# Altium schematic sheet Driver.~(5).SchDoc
size A4
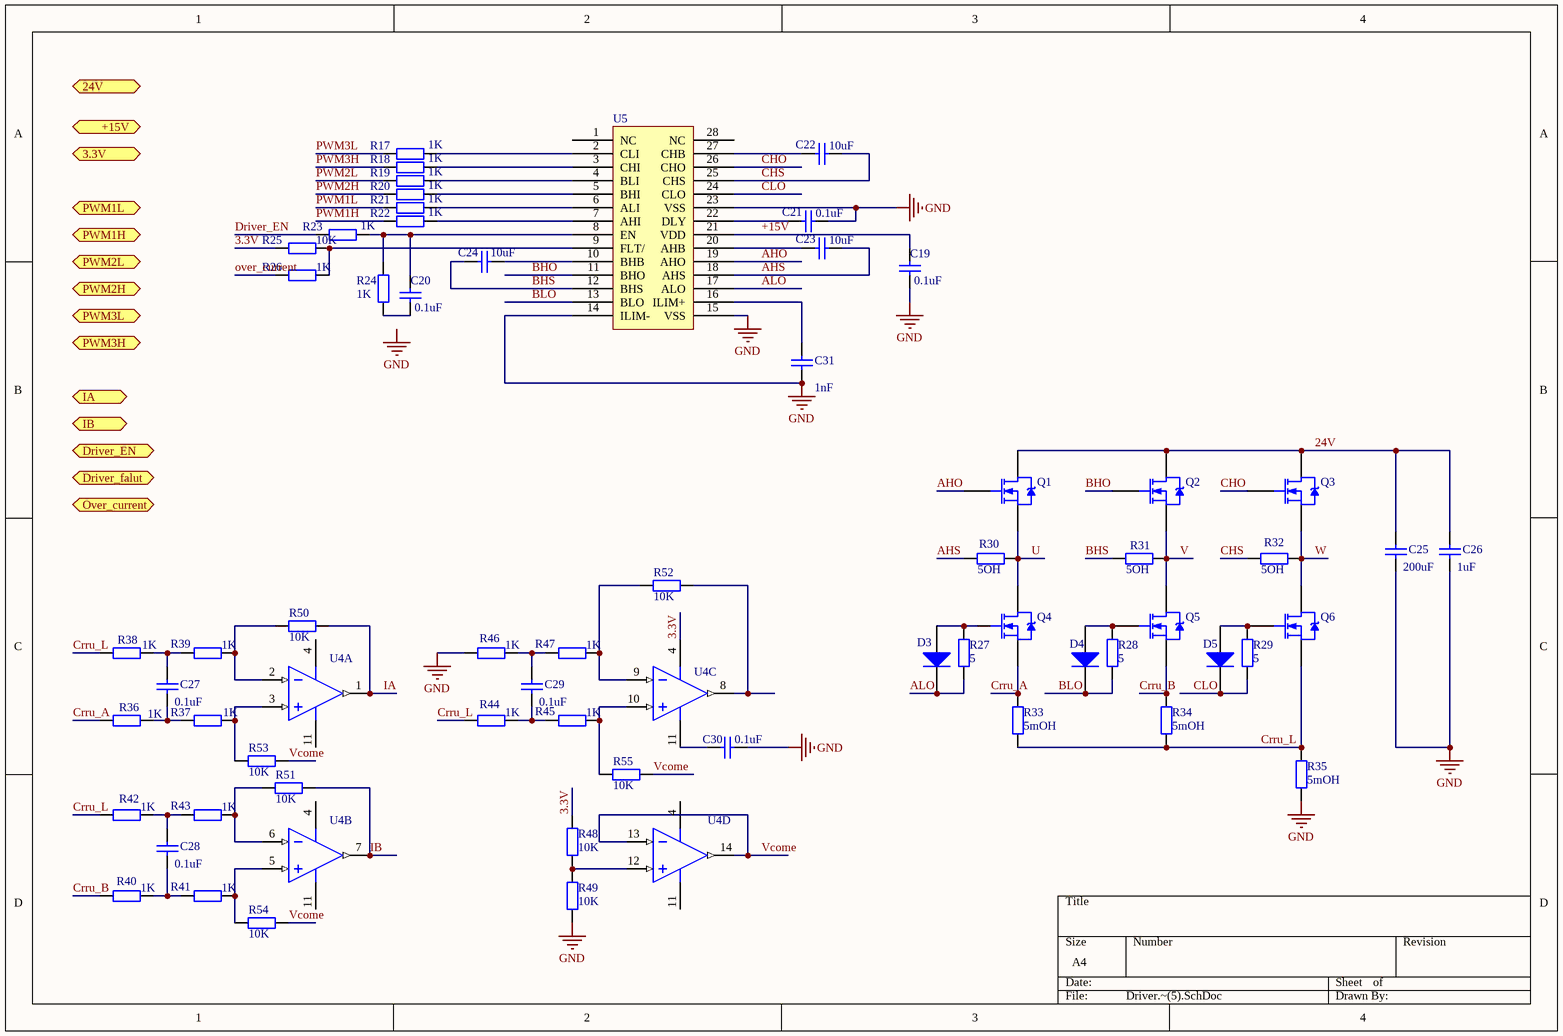
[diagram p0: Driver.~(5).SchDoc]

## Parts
C19  value 0.1uF  [C1206]
C20  value 0.1uF  [C1206]
C21  value 0.1uF  [C1206]
C22  value 10uF  [C1206]
C23  value 10uF  [C1206]
C24  value 10uF  [C1206]
C25  value 200uF  [C1206]
C26  value 1uF  [C1206]
C27  value 0.1uF  [C1206]
C28  value 0.1uF  [C1206]
C29  value 0.1uF  [C1206]
C30  value 0.1uF  [C1206]
C31  value 1nF  [C1206]
D3  Diode BAS16  [SOT-23_N]  (value not drawn)
D4  Diode BAS16  [SOT-23_N]  (value not drawn)
D5  Diode BAS16  [SOT-23_N]  (value not drawn)
Q1  NMOS-2  [TO-220AB]  (value not drawn)
Q2  NMOS-2  [TO-220AB]  (value not drawn)
Q3  NMOS-2  [TO-220AB]  (value not drawn)
Q4  NMOS-2  [TO-220AB]  (value not drawn)
Q5  NMOS-2  [TO-220AB]  (value not drawn)
Q6  NMOS-2  [TO-220AB]  (value not drawn)
R17  value 1K  [AXIAL-0.4]  (hidden comment: Res2)
R18  value 1K  [AXIAL-0.4]  (hidden comment: Res2)
R19  value 1K  [AXIAL-0.4]  (hidden comment: Res2)
R20  value 1K  [AXIAL-0.4]  (hidden comment: Res2)
R21  value 1K  [AXIAL-0.4]  (hidden comment: Res2)
R22  value 1K  [AXIAL-0.4]  (hidden comment: Res2)
R23  value 1K  [AXIAL-0.4]  (hidden comment: Res2)
R24  value 1K  [AXIAL-0.4]  (hidden comment: Res2)
R25  value 10K  [AXIAL-0.4]  (hidden comment: Res2)
R26  value 1K  [AXIAL-0.4]  (hidden comment: Res2)
R27  value 5  [AXIAL-0.4]  (hidden comment: Res2)
R28  value 5  [AXIAL-0.4]  (hidden comment: Res2)
R29  value 5  [AXIAL-0.4]  (hidden comment: Res2)
R30  value 5OH  [AXIAL-0.4]  (hidden comment: Res2)
R31  value 5OH  [AXIAL-0.4]  (hidden comment: Res2)
R32  value 5OH  [AXIAL-0.4]  (hidden comment: Res2)
R33  value 5mOH  [AXIAL-0.4]  (hidden comment: Res2)
R34  value 5mOH  [AXIAL-0.4]  (hidden comment: Res2)
R35  value 5mOH  [AXIAL-0.4]  (hidden comment: Res2)
R36  value 1K  [AXIAL-0.4]  (hidden comment: Res2)
R37  value 1K  [AXIAL-0.4]  (hidden comment: Res2)
R38  value 1K  [AXIAL-0.4]  (hidden comment: Res2)
R39  value 1K  [AXIAL-0.4]  (hidden comment: Res2)
R40  value 1K  [AXIAL-0.4]  (hidden comment: Res2)
R41  value 1K  [AXIAL-0.4]  (hidden comment: Res2)
R42  value 1K  [AXIAL-0.4]  (hidden comment: Res2)
R43  value 1K  [AXIAL-0.4]  (hidden comment: Res2)
R44  value 1K  [AXIAL-0.4]  (hidden comment: Res2)
R45  value 1K  [AXIAL-0.4]  (hidden comment: Res2)
R46  value 1K  [AXIAL-0.4]  (hidden comment: Res2)
R47  value 1K  [AXIAL-0.4]  (hidden comment: Res2)
R48  value 10K  [AXIAL-0.4]  (hidden comment: Res2)
R49  value 10K  [AXIAL-0.4]  (hidden comment: Res2)
R50  value 10K  [AXIAL-0.4]  (hidden comment: Res2)
R51  value 10K  [AXIAL-0.4]  (hidden comment: Res2)
R52  value 10K  [AXIAL-0.4]  (hidden comment: Res2)
R53  value 10K  [AXIAL-0.4]  (hidden comment: Res2)
R54  value 10K  [AXIAL-0.4]  (hidden comment: Res2)
R55  value 10K  [AXIAL-0.4]  (hidden comment: Res2)
U4  MCP6024-E/ST  [TSSOP-ST14_N]  (value not drawn)  (parts A,B,C,D of 4)
U5  MIC4607-1  (value not drawn)

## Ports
3.3V, 24V, +15V, Driver_EN, Driver_falut, IA, IB, Over_current, PWM1H, PWM1L, PWM2H, PWM2L, PWM3H, PWM3L

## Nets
GND: C19.1 C21.1 C25.2 C26.2 C30.2 C31.1 R35.2 R46.1 R49.1 U5.14(ILIM-) U5.15(VSS) U5.23(VSS)
3.3V: R25.1 R48.2 U4.4(VDD)
24V: C25.1 C26.1 Q1.2(D) Q2.2(D) Q3.2(D)
+15V: C19.2 U5.21(VDD)
AHO: Q1.1(G) U5.19(AHO)
AHS: C23.1 R30.2 U5.18(AHS)
ALO: D3.3(K) R27.1 U5.17(ALO)
BHO: Q2.1(G) U5.11(BHO)
BHS: C24.1 R31.2 U5.12(BHS)
BLO: D4.3(K) R28.1 U5.13(BLO)
CHO: Q3.1(G) U5.26(CHO)
CHS: C22.1 R32.2 U5.25(CHS)
CLO: D5.3(K) R29.1 U5.24(CLO)
Crru_A: Q4.3(S) R33.1 R36.1
Crru_B: Q5.3(S) R34.1 R40.1
Crru_L: Q6.3(S) R33.2 R34.2 R35.1 R38.1 R42.1 R44.1
Driver_EN: R23.2
IA: R50.1 U4.1(VOUTA)
IB: R51.1 U4.7(VOUTB)
over_current: R26.1
PWM1H: R22.2
PWM1L: R21.2
PWM2H: R20.2
PWM2L: R19.2
PWM3H: R18.2
PWM3L: R17.2
U: Q1.3(S) Q4.2(D) R30.1
V: Q2.3(S) Q5.2(D) R31.1
Vcome: R53.1 R54.1 R55.1 U4.13(VIND-) U4.14(VOUTD)
W: Q3.3(S) Q6.2(D) R32.1
NetC20_1: C20.1 R24.2
NetC20_2: C20.2 R23.1 R24.1 U5.8(EN)
NetC21_2: C21.2 U5.22(DLY)
NetC22_2: C22.2 U5.27(CHB)
NetC23_2: C23.2 U5.20(AHB)
NetC24_2: C24.2 U5.10(BHB)
NetC27_1: C27.1 R38.2 R39.1
NetC27_2: C27.2 R36.2 R37.1
NetC28_1: C28.1 R42.2 R43.1
NetC28_2: C28.2 R40.2 R41.1
NetC29_1: C29.1 R46.2 R47.1
NetC29_2: C29.2 R44.2 R45.1
NetC30_1: C30.1 U4.11(VSS)
NetC31_2: C31.2 U5.16(ILIM+)
NetD3_1: D3.1(A) Q4.1(G) R27.2
NetD4_1: D4.1(A) Q5.1(G) R28.2
NetD5_1: D5.1(A) Q6.1(G) R29.2
NetR17_1: R17.1 U5.2(CLI)
NetR18_1: R18.1 U5.3(CHI)
NetR19_1: R19.1 U5.4(BLI)
NetR20_1: R20.1 U5.5(BHI)
NetR21_1: R21.1 U5.6(ALI)
NetR22_1: R22.1 U5.7(AHI)
NetR25_2: R25.2 R26.2 U5.9(FLT/)
NetR37_2: R37.2 R53.2 U4.3(VINA+)
NetR39_2: R39.2 R50.2 U4.2(VINA-)
NetR41_2: R41.2 R54.2 U4.5(VINB+)
NetR43_2: R43.2 R51.2 U4.6(VINB-)
NetR45_2: R45.2 R55.2 U4.10(VINC+)
NetR47_2: R47.2 R52.2 U4.9(VINC-)
NetR48_1: R48.1 R49.2 U4.12(VIND+)
NetR52_1: R52.1 U4.8(VOUTC)

Not connected (* = marked no-connect by the designer): U5 1(NC) 28(NC)

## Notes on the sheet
- Labels drawn without touching a wire or pin: GND

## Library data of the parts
C19-C31 = Cap Semi: Capacitor (Semiconductor SIM Model)
D3-D5 = Diode BAS16: Silicon Switching Diode for High-Speed Switching; Note: Pin 2 is not connected and not drawn.
Q1-Q6 = NMOS-2: N-Channel Power MOSFET; Note: Pin 2 is electrically connected to pin 4.
R17-R55 = Res2: Resistor
U4 = MCP6024-E/ST: Rail-to-Rail Input/Output, 10 MHz Operational Amplifier, 14-Pin TSSOP, Extended Temperature; Manufacturer: Microchip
